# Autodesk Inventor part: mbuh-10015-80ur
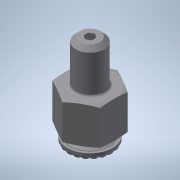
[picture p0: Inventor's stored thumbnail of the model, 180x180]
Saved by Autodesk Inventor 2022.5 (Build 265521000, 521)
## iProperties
Created: 2017-08
Part Number: mbuh-10015-80ur
Material: 一般
Document SubType Name: Modeling
Designer: imaocorp
Density: 1 g/cm^3
Appearance: 既定
Author: imaocorp
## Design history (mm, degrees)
node "mbuh-10015-80ur.x_t1"
node "mbuh-10015-80ur"
node "Base1"
